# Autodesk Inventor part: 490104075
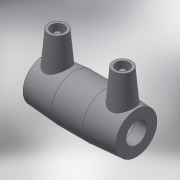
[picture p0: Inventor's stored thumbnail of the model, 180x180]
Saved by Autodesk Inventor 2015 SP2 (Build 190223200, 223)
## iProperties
Created: 2017-06
Part Number: 490104075
Material: Generic
Description: PLASSON COUPLER 75-75
Document SubType Name: Modeling
Designer: KIM
Mass: 55.0731 g
Surface Area: 148.067 cm^2
Volume: 55.0731 cm^3
Density: 1 g/cm^3
Appearance: Default
Author: KIM
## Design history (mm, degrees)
derived "490104.ipt"
feature "Solid1::490104.ipt"
tag "TaggingFeature1"
body "Solid1"
other parameters: "d0" = 126, "d1" = 75, "d2" = 98, "d3" = 61, "d4" = 42, "d5" = 88.2, "d6" = 71.25, "d7" = 75, "d8" = 168 deg, "d10" = 24.4, "d11" = 8.13333, "d13" = 126, "d14" = 17.6296, "d15" = 61, "d16" = 61, "d17" = 71.25, "d18" = 75, "d19" = 3.52592, "d20" = 168 deg, "d22" = 92.12, "d23" = 98, "d24" = 89.3564, "d25" = 135 deg, "d26" = 50.4, "d27" = 135 deg, "d29" = 64, "d30" = 14, "d31" = 44.1, "d34" = 5 deg, "d35" = 15, "d39" = 5 deg, "d41" = 4, "d42" = 14, "d43" = 0, "d45" = 4, "d46" = 14, "d47" = 0, "d48" = 3, "d49" = 0, "d50" = 3, "d51" = 0, "d52" = 17.69, "d53" = 4.4225, "d_" = 75, "L_" = 126, "L_1" = 61, "D_" = 98, "A_" = 64, "d_2" = 12
